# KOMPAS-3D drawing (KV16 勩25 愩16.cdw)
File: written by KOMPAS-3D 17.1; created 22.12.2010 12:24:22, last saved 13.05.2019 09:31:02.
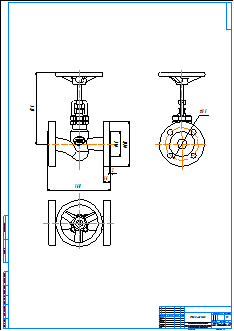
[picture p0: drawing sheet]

Title block, sheet 1: name: KV16 Ду25 Ру16; material: Внимание! Данный продукт является объектом авторского права ООО «Торговый Дом АДЛ». / Запрещается изменение, копирование, распространение / (в том числе путем копирования на другие сайты и ресурсы в Интернете) / или любое иное использование информации и объектов без предварительного / согласия правообладателя (ООО «Торговый Дом АДЛ»).; scale: 1:1; sheets: 1; organisation: ООО "Торговый дом АДЛ"; sheet format: A1; stored path: \\adlc.lan\data\АДЛ_ПКД\3D-модели\ADL production\Вентили ГРАНВЕНТ\KV16\KOMPAS 2D\KV16 Ду25 Ру16.cdw

Views: Вид 4, Спереди 1, Проекционный вид 3
Dimensions and other numbers on the sheet: 65; 115; 2; 16; 160; 85; 183; 1:1; 1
